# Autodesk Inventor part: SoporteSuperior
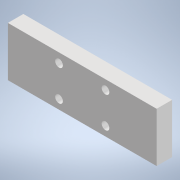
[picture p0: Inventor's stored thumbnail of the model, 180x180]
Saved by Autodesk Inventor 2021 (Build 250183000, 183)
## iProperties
Created: 2021-02
Part Number: SoporteSuperior
Material: Genérico
Document SubType Name: Modeling
Designer: ATOUZA
Density: 1 g/cm^3
Appearance: Valor por defecto
Author: ATOUZA
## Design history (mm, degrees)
sketch "Boceto1"
  geometry: L1 (-48, -16)-(48, -16); L2 (48, -16)-(48, 16); L3 (48, 16)-(-48, 16); L4 (-48, 16)-(-48, -16); L5 (-48, -16)-(48, 16); L6 (48, -16)-(-48, 16); L7 (-48, 0)-(48, 0); L8 (0, 16)-(0, -16); C1 r 2.5 at (-15, 10); C2 r 2.5 at (-15, -10); C3 r 2.5 at (15, 10); C4 r 2.5 at (15, -10); C5 r 5 at (-25, 0); C6 r 5 at (25, 0); 1 further point
  constraints: 16 end point, 6 centre point, 6 midpoint, 4 symmetric about line, 2 parallel, 1 horizontal, 1 perpendicular, 1 point on line, 4 other
  dimensions: "d0" = 96 distance of L3.end L2.end; "d1" = 32 distance of L2.end L1.end; "d2" = 5 diameter of C1; "d4" = 15 distance from line of L8 C1.centre; "d5" = 10 distance from line of L7 C1.centre; "d8" = 10 diameter of C5; "d9" = 25 distance from line of L8 C5.centre
extrude "Extrusión1" new body sketch "Boceto1" distance "d6" = 10; taper "d7" = 0 deg
node "Sólido1"
